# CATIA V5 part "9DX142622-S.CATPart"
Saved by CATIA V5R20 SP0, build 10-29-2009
Part number: 9DX142622-S
Revision: ANY
Definition: UNKNOWN
Nomenclature: 9DX142622-S
Source: Unknown
Bounding box of the stored display mesh (mm): x -3 to 3, y -2.5 to 2.5, z -11.4 to -6.433
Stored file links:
  C:\Users\Utente\Desktop\IO LAVORO\3D X SITO CF\CUMSA\3D files DX\DX 142622\9DX142622-S.CATPart
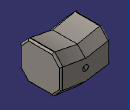
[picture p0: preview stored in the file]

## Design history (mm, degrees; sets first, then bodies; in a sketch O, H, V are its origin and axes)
Body1 "Diámetro de taladro Ø0.7 (0.7)1" (main body)
  Solid1: solid without history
